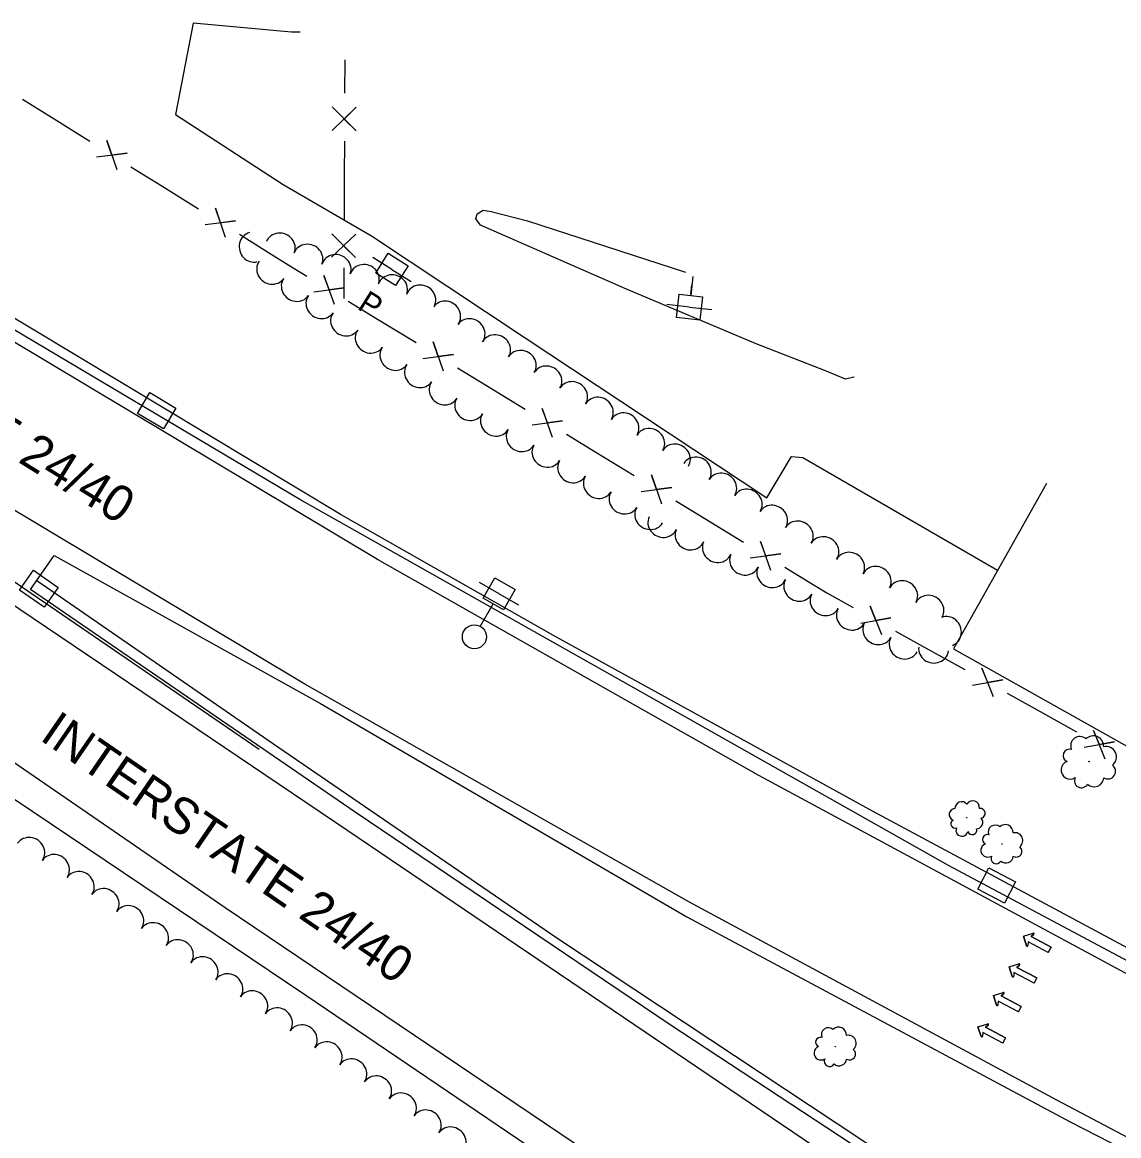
# Model space of a CAD drawing. Extents: x 1746010 to 1754829, y 655801 to 663091.
# Drawn here: x 1751132 to 1751496.6, y 659369.9 to 659740.2 of the extents above; entities that cross this region are included whole.
import ezdxf

# ---------------------------------------------------------------- set-up
doc = ezdxf.new("R2010")
doc.units = 0
for name, color, linetype in [('SURVEY - AERIAL SURVEY - Photo Control - Points - Elevations', 7, 'Continuous'), ('SURVEY - AERIAL SURVEY - Photo Control - Points - Locators', 7, 'Continuous'), ('SURVEY - AERIAL SURVEY - Photo Control - Points - Numbers', 7, 'Continuous'), ('SURVEY - CENTERLINE - Existing Roads - Development', 7, 'Continuous'), ('SURVEY - CENTERLINE - Existing Roads Curve Text', 7, 'Continuous'), ('SURVEY - CENTERLINE - Existing Roads Text', 7, 'Continuous'), ('SURVEY - CENTERLINE - Preliminary - Development', 7, 'Continuous'), ('SURVEY - CONTROL - Points - Numbers', 7, 'Continuous'), ('SURVEY - DRAINAGE - Area Shapes - Points - Elevations', 7, 'Continuous')]:
    doc.layers.add(name, color=color, linetype=linetype)

msp = doc.modelspace()

# ---------------------------------------------------------------- linework, layer by layer
at = {"layer": 'SURVEY - AERIAL SURVEY - Photo Control - Points - Elevations'}
for points in [[(1751901.75, 659229.66), (1751903.78, 659232.49), (1751820.15, 659271.12), (1751720.09, 659319), (1751608.79, 659375.48), (1751511.86, 659425.67), (1751414.79, 659477.82), (1751309.42, 659535.79), (1751238.02, 659576.37), (1751119.98, 659647.33), (1751011.07, 659715.27), (1750920.63, 659773.68), (1750818.05, 659842.07), (1750688.97, 659930.51), (1750687.2, 659926.86)], [(1751136.82, 659554.52), (1751217.01, 659499.16), (1751310.15, 659435.49), (1751402.66, 659374.15), (1751479.7, 659322.87), (1751569.69, 659263.28), (1751658.69, 659205.51), (1751718.84, 659164.93), (1751717.79, 659161.8)]]:
    msp.add_lwpolyline(points, dxfattribs=at)
at = {"layer": 'SURVEY - AERIAL SURVEY - Photo Control - Points - Locators'}
for points in [[(1751850.89, 659069.97), (1751836.71, 659078.71), (1751698.09, 659167.45), (1751556.82, 659259.91), (1751409.51, 659356.6), (1751240.26, 659471.26), (1751108.21, 659560.28), (1750949.44, 659670.61), (1750790.01, 659782.16), (1750639.25, 659888.39), (1750537.27, 659960.87), (1750507.28, 659982.53)], [(1751692.52, 659270.52), (1751605.65, 659313.28), (1751476.09, 659381.66), (1751353.72, 659447.67), (1751225.98, 659520.03), (1751088.26, 659602.44), (1750950.33, 659687.25), (1750831.52, 659764.33), (1750532.19, 659979.6)], [(1751980.95, 659190.5), (1751865.03, 659241.97), (1751755.82, 659292.86), (1751627.46, 659356.04), (1751498.69, 659424), (1751376.94, 659489.68), (1751250.14, 659561.52), (1751113.15, 659643.48), (1750975.97, 659727.83), (1750858.05, 659804.33), (1750722.4, 659896.24), (1750620.83, 659969.19)], [(1751811.46, 659040.6), (1751803.54, 659045.66), (1751651.7, 659139.14), (1751560.97, 659192.86), (1751430.95, 659277.83), (1751226.31, 659416.5), (1751044.68, 659538.71), (1750870.37, 659656.91), (1750693.9, 659781.14), (1750567.77, 659872.76), (1750445.81, 659959.59)], [(1750464.75, 659959.09), (1750533.91, 659909.95), (1750645.13, 659831.38), (1750753.4, 659754.5), (1750870.59, 659672.13), (1750959.5, 659609.93), (1751081.2, 659527.03), (1751199.52, 659445.74), (1751320.31, 659364.23), (1751443.12, 659281.31), (1751559.93, 659204.83), (1751660.4, 659140.92), (1751744.29, 659087.1), (1751814.04, 659042.53)], [(1751981.66, 659195.26), (1751889.68, 659234.85), (1751784.21, 659284.64), (1751694.2, 659328.1), (1751603.81, 659373.71), (1751512.94, 659420.78), (1751440.06, 659459.77), (1751340.52, 659515.91), (1751224.32, 659581.45), (1751125.19, 659640.31), (1751025.2, 659702.76), (1750930.86, 659762.02), (1750841.47, 659821.93), (1750746.73, 659885.97), (1750687.69, 659926.53)], [(1751224.47, 659736.87), (1751221.58, 659736.85), (1751188.82, 659739.9), (1751182.93, 659709.49), (1751218.82, 659686.26), (1751248.12, 659669.14), (1751298.87, 659635.5), (1751379.63, 659582), (1751387.79, 659595.81), (1751391.61, 659595.38), (1751456.36, 659557.92)], [(1751376.09, 659633.26), (1751332.92, 659651.45), (1751284.36, 659672.67), (1751282.87, 659674.84), (1751283.25, 659676.45), (1751285.24, 659677.69), (1751287.96, 659677.28), (1751300, 659674.11), (1751352.57, 659657.11)], [(1751408.55, 659622.25), (1751408.51, 659622.2), (1751405.76, 659621.5), (1751399.09, 659624.29), (1751376.09, 659633.26)], [(1751855.66, 659073.53), (1751824.49, 659092.89), (1751720.6, 659159.95), (1751578.18, 659253.97), (1751455.85, 659335.43), (1751347.45, 659406.77), (1751242.7, 659477.43), (1751134.7, 659551.49), (1751142.63, 659562.83), (1751231.24, 659513.59), (1751353.03, 659442.63), (1751480.52, 659374.44), (1751556.22, 659335.73), (1751679.55, 659272.32), (1751784.68, 659222.03), (1751889.47, 659172.35), (1751954.53, 659146.62)]]:
    msp.add_lwpolyline(points, dxfattribs=at)
at = {"layer": 'SURVEY - AERIAL SURVEY - Photo Control - Points - Numbers'}
msp.add_lwpolyline([(1751210.77, 659498.28), (1751086.47, 659583.36), (1750914.66, 659701.33), (1750734.42, 659828.18), (1750551.67, 659956.79), (1750517.76, 659981.3)], dxfattribs=at)
at = {"layer": 'SURVEY - CENTERLINE - Existing Roads - Development'}
for points in [[(1751239.28, 659727.65), (1751239.22, 659716.64)], [(1751132.1, 659714.64), (1751141.78, 659708.61)], [(1751235.11, 659712.04), (1751243.05, 659704.08), (1751239.08, 659708.01), (1751243.09, 659711.92), (1751235.08, 659704.2)], [(1751141.78, 659708.61), (1751154.51, 659700.67)], [(1751156.74, 659695.39), (1751166.86, 659696.66), (1751161.84, 659696), (1751160.16, 659700.84), (1751163.45, 659691.21)], [(1751239.15, 659700.67), (1751239.09, 659689.35)], [(1751168.17, 659692.15), (1751177.84, 659686.12)], [(1751239.09, 659689.35), (1751239.02, 659674.47)], [(1751177.84, 659686.12), (1751190.57, 659678.18)], [(1751192.81, 659672.9), (1751202.93, 659674.17), (1751197.91, 659673.51), (1751196.22, 659678.35), (1751199.51, 659668.72)], [(1751204.23, 659669.66), (1751213.91, 659663.63)], [(1751234.91, 659669.87), (1751242.84, 659661.91), (1751238.88, 659665.84), (1751242.88, 659669.75), (1751234.87, 659662.03)], [(1751213.91, 659663.63), (1751220.7, 659659.39), (1751226.67, 659655.75)], [(1751238.94, 659658.49), (1751238.89, 659648.31)], [(1751228.94, 659650.51), (1751239.09, 659651.86), (1751234.06, 659651.16), (1751232.34, 659655.97), (1751235.69, 659646.4)], [(1751240.42, 659647.38), (1751250.15, 659641.44)], [(1751250.15, 659641.44), (1751262.96, 659633.64)], [(1751265.23, 659628.39), (1751275.38, 659629.74), (1751270.35, 659629.04), (1751268.63, 659633.85), (1751271.97, 659624.28)], [(1751276.71, 659625.26), (1751286.44, 659619.33)], [(1751286.44, 659619.33), (1751299.25, 659611.52)], [(1751301.52, 659606.28), (1751311.67, 659607.62), (1751306.64, 659606.92), (1751304.92, 659611.73), (1751308.26, 659602.17)], [(1751313, 659603.14), (1751322.73, 659597.21)], [(1751322.73, 659597.21), (1751335.54, 659589.4)], [(1751337.81, 659584.16), (1751347.96, 659585.51), (1751342.93, 659584.81), (1751341.21, 659589.62), (1751344.55, 659580.05)], [(1751472.56, 659586.76), (1751441.7, 659531.82), (1751724.76, 659372.8), (1751757.41, 659430.92)], [(1751349.29, 659581.02), (1751359.02, 659575.09)], [(1751359.02, 659575.09), (1751371.83, 659567.29)], [(1751374.1, 659562.04), (1751384.25, 659563.39), (1751379.22, 659562.69), (1751377.5, 659567.5), (1751380.84, 659557.93)], [(1751385.58, 659558.91), (1751395.31, 659552.97)], [(1751395.31, 659552.97), (1751399.54, 659550.4), (1751408.32, 659545.52)], [(1751410.81, 659540.36), (1751420.88, 659542.13), (1751415.89, 659541.22), (1751413.97, 659545.96), (1751417.72, 659536.53)], [(1751422.4, 659537.7), (1751432.36, 659532.16)], [(1751432.36, 659532.16), (1751445.48, 659524.88)], [(1751447.97, 659519.73), (1751458.03, 659521.49), (1751453.04, 659520.58), (1751451.12, 659525.33), (1751454.87, 659515.89)], [(1751459.55, 659517.06), (1751469.52, 659511.52)], [(1751469.52, 659511.52), (1751482.63, 659504.24)], [(1751485.12, 659499.09), (1751495.18, 659500.85), (1751490.2, 659499.95), (1751488.28, 659504.69), (1751492.02, 659495.25)]]:
    msp.add_lwpolyline(points, dxfattribs=at)
at = {"layer": 'SURVEY - CENTERLINE - Existing Roads Curve Text'}
for p, q in [((1751254.95, 659657.98), (1751248.6, 659661.98)), ((1751254.95, 659657.98), (1751261.29, 659653.99)), ((1751354.98, 659655.61), (1751354.28, 659649.32)), ((1751354.33, 659649.71), (1751354.68, 659652.89)), ((1751353.85, 659645.44), (1751346.4, 659646.27)), ((1751353.85, 659645.44), (1751361.3, 659644.61)), ((1751290.55, 659550.12), (1751284.05, 659553.84)), ((1751290.55, 659550.12), (1751297.06, 659546.39)), ((1751284.3, 659539.18), (1751288.62, 659546.73)), ((1751288.42, 659546.39), (1751286.83, 659543.61))]:
    msp.add_line(p, q, dxfattribs=at)
for points in [[(1751253.72, 659663.36), (1751260.32, 659659.21), (1751256.17, 659652.6), (1751249.57, 659656.76)], [(1751349.54, 659641.99), (1751350.41, 659649.75), (1751358.16, 659648.88), (1751357.29, 659641.13)], [(1751295.88, 659551.57), (1751292, 659544.8), (1751285.23, 659548.67), (1751289.11, 659555.44)]]:
    msp.add_lwpolyline(points, close=True, dxfattribs=at)
msp.add_circle((1751282.36, 659535.8), 4, dxfattribs=at)
at = {"layer": 'SURVEY - CENTERLINE - Existing Roads Text'}
for centre, radius in [((1751486.73, 659494.31), 0.106), ((1751446.1, 659475.65), 0.0699), ((1751457.8, 659466.9), 0.0804), ((1751402.37, 659399.48), 0.0809)]:
    msp.add_circle(centre, radius, dxfattribs=at)
for centre, radius, start, end in [((1751483.68, 659499.58), 3.05, 47.9365, 204.7255), ((1751488.15, 659499.37), 3.47, 356.9893, 134.5135), ((1751480.2, 659496.33), 2.09, 70.0527, 248.7983), ((1751492.44, 659495.83), 3.45, 307.8851, 103.7236), ((1751480.48, 659491.52), 3.04, 110.0734, 303.4931), ((1751493.03, 659491.07), 2.55, 238.138, 53.1383), ((1751484.22, 659487.93), 2.32, 152.6921, 330.0112), ((1751488.42, 659489.2), 3.28, 227.9791, 354.8248), ((1751444.42, 659478.66), 2.28, 41.9075, 179.4317), ((1751448.05, 659479), 2.27, 352.8033, 148.6418), ((1751442.24, 659476.68), 2, 92.8547, 249.6437), ((1751450.53, 659477.06), 1.67, 283.0562, 98.0565), ((1751442.12, 659473.56), 1.37, 114.9709, 293.7165), ((1751444.49, 659471.45), 2, 154.9916, 348.4113), ((1751449.26, 659474.06), 2.16, 272.8973, 39.743), ((1751455.5, 659470.88), 2.3, 47.9365, 204.7255), ((1751458.87, 659470.72), 2.62, 356.9893, 134.5135), ((1751447.89, 659471.51), 1.52, 197.6103, 14.9294), ((1751452.86, 659468.43), 1.58, 70.0527, 248.7983), ((1751462.11, 659468.05), 2.61, 307.8851, 103.7236), ((1751453.08, 659464.8), 2.3, 110.0734, 303.4931), ((1751462.56, 659464.45), 1.92, 238.138, 53.1383), ((1751455.9, 659462.08), 1.75, 152.6921, 330.0112), ((1751459.08, 659463.05), 2.48, 227.9791, 354.8248), ((1751400.05, 659403.48), 2.32, 47.9365, 204.7255), ((1751403.45, 659403.33), 2.64, 356.9893, 134.5135), ((1751397.4, 659401.02), 1.59, 70.0527, 248.7983), ((1751406.71, 659400.64), 2.62, 307.8851, 103.7236), ((1751397.62, 659397.36), 2.31, 110.0734, 303.4931), ((1751407.16, 659397.02), 1.94, 238.138, 53.1383), ((1751400.46, 659394.63), 1.76, 152.6921, 330.0112), ((1751403.65, 659395.6), 2.49, 227.9791, 354.8248)]:
    msp.add_arc(centre, radius, start, end, dxfattribs=at)
for centre, major_axis in [((1751208.87, 659665.4), (-1.31, 4.83)), ((1751217.82, 659665.34), (4.63, -1.88)), ((1751227.02, 659661.61), (4.63, -1.88)), ((1751236.39, 659658.2), (4.71, -1.67)), ((1751214.87, 659657.88), (-4.1, 2.87)), ((1751245.79, 659654.87), (4.7, -1.71)), ((1751223.06, 659652.15), (-4.1, 2.87)), ((1751255.17, 659651.46), (4.7, -1.71)), ((1751264.55, 659648.05), (4.7, -1.71)), ((1751231.26, 659646.42), (-4.1, 2.87)), ((1751272.89, 659642.65), (4.05, -2.93)), ((1751239.45, 659640.68), (-4.1, 2.87)), ((1751281, 659636.79), (4.05, -2.93)), ((1751247.65, 659634.95), (-4.1, 2.87)), ((1751289.45, 659631.46), (4.27, -2.6)), ((1751255.84, 659629.22), (-4.1, 2.87)), ((1751297.99, 659626.27), (4.27, -2.6)), ((1751264.03, 659623.49), (-4.1, 2.87)), ((1751306.54, 659621.08), (4.27, -2.6)), ((1751272.23, 659617.75), (-4.1, 2.87)), ((1751315.08, 659615.88), (4.27, -2.6)), ((1751280.76, 659612.54), (-4.28, 2.59)), ((1751323.63, 659610.69), (4.27, -2.6)), ((1751289.31, 659607.35), (-4.28, 2.59)), ((1751332.17, 659605.5), (4.27, -2.6)), ((1751340.72, 659600.31), (4.27, -2.6)), ((1751297.86, 659602.17), (-4.28, 2.59)), ((1751306.42, 659596.99), (-4.28, 2.59)), ((1751349.26, 659595.12), (4.27, -2.6)), ((1751356.23, 659590.79), (4.23, -2.67)), ((1751314.97, 659591.8), (-4.28, 2.59)), ((1751364.68, 659585.45), (4.23, -2.67)), ((1751323.52, 659586.62), (-4.28, 2.59)), ((1751332.07, 659581.43), (-4.28, 2.59)), ((1751373.14, 659580.11), (4.23, -2.67)), ((1751381.59, 659574.77), (4.23, -2.67)), ((1751340.62, 659576.25), (-4.28, 2.59)), ((1751344.99, 659573.62), (-4.54, 2.09)), ((1751390.09, 659569.5), (4.27, -2.61)), ((1751354.05, 659569.44), (-4.54, 2.09)), ((1751398.63, 659564.29), (4.27, -2.61)), ((1751363.11, 659565.27), (-4.54, 2.09)), ((1751372.17, 659561.09), (-4.54, 2.09)), ((1751407.2, 659559.14), (4.41, -2.36)), ((1751381.23, 659556.91), (-4.54, 2.09)), ((1751416.02, 659554.42), (4.41, -2.36)), ((1751390.15, 659552.42), (-4.38, 2.41)), ((1751424.83, 659549.69), (4.37, -2.44)), ((1751433.56, 659544.82), (4.37, -2.44)), ((1751398.91, 659547.61), (-4.38, 2.41)), ((1751407.68, 659542.79), (-4.38, 2.41)), ((1751439.54, 659537.58), (1.82, -4.66)), ((1751416.44, 659537.98), (-4.38, 2.41)), ((1751425.21, 659533.17), (-4.38, 2.41)), ((1751435.07, 659531.77), (-4.96, 0.62)), ((1751134.58, 659464.27), (4.12, -2.84)), ((1751142.81, 659458.6), (4.12, -2.84)), ((1751151.05, 659452.93), (4.12, -2.84)), ((1751159.29, 659447.26), (4.12, -2.84)), ((1751167.53, 659441.59), (4.12, -2.84)), ((1751175.76, 659435.92), (4.12, -2.84)), ((1751184, 659430.25), (4.12, -2.84)), ((1751192.24, 659424.58), (4.12, -2.84)), ((1751200.48, 659418.92), (4.12, -2.83)), ((1751208.73, 659413.26), (4.12, -2.83)), ((1751216.97, 659407.6), (4.12, -2.83)), ((1751225.22, 659401.94), (4.12, -2.83)), ((1751233.46, 659396.28), (4.12, -2.83)), ((1751241.71, 659390.62), (4.12, -2.83)), ((1751249.95, 659384.96), (4.12, -2.83)), ((1751258.2, 659379.3), (4.12, -2.83)), ((1751266.44, 659373.64), (4.12, -2.83)), ((1751274.69, 659367.98), (4.12, -2.83))]:
    msp.add_ellipse(centre, major_axis=major_axis, ratio=0.940188, start_param=0, end_param=3.141593, dxfattribs=at)
at = {"layer": 'SURVEY - CENTERLINE - Preliminary - Development'}
for p, q in [((1751176.72, 659611.01), (1751176.72, 659611.01)), ((1751137.52, 659551.77), (1751137.52, 659551.77)), ((1751456.02, 659453.1), (1751456.02, 659453.1))]:
    msp.add_line(p, q, dxfattribs=at)
for points in [[(1751170.38, 659610.12), (1751174.47, 659617), (1751183.06, 659611.89), (1751178.97, 659605.01), (1751170.38, 659610.12)], [(1751131.13, 659551.36), (1751135.72, 659557.92), (1751143.91, 659552.18), (1751139.33, 659545.63), (1751131.13, 659551.36)], [(1751449.74, 659451.86), (1751453.43, 659458.96), (1751462.3, 659454.35), (1751458.61, 659447.25), (1751449.74, 659451.86)]]:
    msp.add_lwpolyline(points, dxfattribs=at)
at = {"layer": 'SURVEY - DRAINAGE - Area Shapes - Points - Elevations'}
for p, q in [((1751464.94, 659436.26), (1751468.16, 659437.28)), ((1751464.94, 659436.26), (1751468.16, 659437.28)), ((1751465.95, 659433.04), (1751464.94, 659436.26)), ((1751464.94, 659436.26), (1751465.95, 659433.04)), ((1751468.39, 659436.86), (1751467.45, 659436.07)), ((1751467.45, 659436.07), (1751468.39, 659436.86)), ((1751467.45, 659436.07), (1751474.12, 659432.6)), ((1751474.12, 659432.6), (1751467.45, 659436.07)), ((1751466.54, 659434.32), (1751466.43, 659433.1)), ((1751466.54, 659434.32), (1751466.43, 659433.1)), ((1751473.21, 659430.85), (1751466.54, 659434.32)), ((1751473.21, 659430.85), (1751466.54, 659434.32)), ((1751474.12, 659432.6), (1751473.21, 659430.85)), ((1751473.21, 659430.85), (1751474.12, 659432.6)), ((1751460.19, 659426.05), (1751463.41, 659427.06)), ((1751460.19, 659426.05), (1751463.41, 659427.06)), ((1751461.21, 659422.82), (1751460.19, 659426.05)), ((1751460.19, 659426.05), (1751461.21, 659422.82)), ((1751463.64, 659426.64), (1751462.7, 659425.85)), ((1751462.7, 659425.85), (1751463.64, 659426.64)), ((1751462.7, 659425.85), (1751469.38, 659422.38)), ((1751469.38, 659422.38), (1751462.7, 659425.85)), ((1751461.79, 659424.1), (1751461.69, 659422.88)), ((1751461.79, 659424.1), (1751461.69, 659422.88)), ((1751468.47, 659420.63), (1751461.79, 659424.1)), ((1751468.47, 659420.63), (1751461.79, 659424.1)), ((1751469.38, 659422.38), (1751468.47, 659420.63)), ((1751468.47, 659420.63), (1751469.38, 659422.38)), ((1751454.98, 659416.53), (1751458.2, 659417.55)), ((1751454.98, 659416.53), (1751458.2, 659417.55)), ((1751458.43, 659417.13), (1751457.49, 659416.34)), ((1751457.49, 659416.34), (1751458.43, 659417.13)), ((1751456, 659413.31), (1751454.98, 659416.53)), ((1751454.98, 659416.53), (1751456, 659413.31)), ((1751456.58, 659414.59), (1751456.47, 659413.36)), ((1751456.58, 659414.59), (1751456.47, 659413.36)), ((1751463.26, 659411.12), (1751456.58, 659414.59)), ((1751463.26, 659411.12), (1751456.58, 659414.59)), ((1751457.49, 659416.34), (1751464.16, 659412.87)), ((1751464.16, 659412.87), (1751457.49, 659416.34)), ((1751464.16, 659412.87), (1751463.26, 659411.12)), ((1751463.26, 659411.12), (1751464.16, 659412.87)), ((1751449.82, 659406.11), (1751453.04, 659407.13)), ((1751449.82, 659406.11), (1751453.04, 659407.13)), ((1751450.84, 659402.89), (1751449.82, 659406.11)), ((1751449.82, 659406.11), (1751450.84, 659402.89)), ((1751453.28, 659406.71), (1751452.33, 659405.92)), ((1751452.33, 659405.92), (1751453.28, 659406.71)), ((1751452.33, 659405.92), (1751459.01, 659402.45)), ((1751459.01, 659402.45), (1751452.33, 659405.92)), ((1751451.43, 659404.17), (1751451.32, 659402.94)), ((1751451.43, 659404.17), (1751451.32, 659402.94)), ((1751458.1, 659400.7), (1751451.43, 659404.17)), ((1751458.1, 659400.7), (1751451.43, 659404.17)), ((1751459.01, 659402.45), (1751458.1, 659400.7)), ((1751458.1, 659400.7), (1751459.01, 659402.45))]:
    msp.add_line(p, q, dxfattribs=at)
for centre, start, end in [((1751468.23, 659437.05), 310.0963, 107.5446), ((1751468.23, 659437.05), 310.0963, 107.5446), ((1751466.19, 659433.12), 197.5446, 355.0378), ((1751466.19, 659433.12), 197.5446, 355.0378), ((1751463.48, 659426.83), 310.0963, 107.5446), ((1751463.48, 659426.83), 310.0963, 107.5446), ((1751461.44, 659422.9), 197.5446, 355.0378), ((1751461.44, 659422.9), 197.5446, 355.0378), ((1751458.27, 659417.31), 310.0963, 107.5446), ((1751458.27, 659417.31), 310.0963, 107.5446), ((1751456.23, 659413.39), 197.5446, 355.0378), ((1751456.23, 659413.39), 197.5446, 355.0378), ((1751453.12, 659406.89), 310.0963, 107.5446), ((1751453.12, 659406.89), 310.0963, 107.5446), ((1751451.08, 659402.97), 197.5446, 355.0378), ((1751451.08, 659402.97), 197.5446, 355.0378)]:
    msp.add_arc(centre, 0.246, start, end, dxfattribs=at)

# ---------------------------------------------------------------- texts
at = {"layer": 'SURVEY - CENTERLINE - Existing Roads Curve Text'}
msp.add_text('P', height=7.48, rotation=327.8175, dxfattribs=at).set_placement((1751243.11, 659644.99))
at = {"layer": 'SURVEY - CONTROL - Points - Numbers'}
for rotation, p in [(328.1505, (1751041.66, 659649.16)), (325.5116, (1751137.45, 659501.73))]:
    msp.add_text('INTERSTATE 24/40', height=12, rotation=rotation, dxfattribs=at).set_placement(p)

doc.saveas('drawing.dxf')
